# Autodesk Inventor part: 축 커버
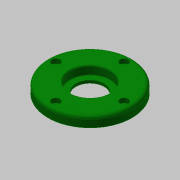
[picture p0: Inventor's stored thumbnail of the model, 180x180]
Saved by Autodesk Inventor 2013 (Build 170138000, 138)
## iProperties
Created: 2015-10
Part Number: 축 커버
Document SubType Name: Modeling
Designer: mdu
Density: 1 g/cm^3
Material: 일반
Author: mdu
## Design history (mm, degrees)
sketch "스케치1"
  geometry: C1 r 40 at (0, 0) reference; C2 r 26 at (0, 0) reference; 1 further point
  node "참조1"
  node "참조2"
extrude "돌출1" new body sketch "스케치1" distance "d0" = 10; taper "d1" = 0 deg
extrude "돌출2" join sketch "스케치1" distance "d2" = 4; taper "d3" = 0 deg
hole "구멍1" diameter "d6" = 27; stored, may be unused: countersink angle "d10" = 90 deg, drill point angle "d12" = 118 deg; dims "d7" = 6, "d8" = 38, "d9" = 8.3, "d11" = 8, "d33" = 10, "d34" = 10
sketch "스케치2"
  geometry: C1 r 20 at (0, 0); 1 further point
  constraints: 1 centre point, 1 coincident
  dimensions: "d13" = 40 diameter of C1
extrude "돌출3" cut sketch "스케치2" distance "d14" = 3; taper "d15" = 0 deg
sketch "스케치3"
  geometry: C1 r 1.621 at (0, 32.5) reference; 1 further point
hole "구멍2" sketch "스케치3" at (0, 32.5) diameter "d16" = 4.5; stored, may be unused: countersink angle "d20" = 90 deg, drill point angle "d22" = 118 deg; dims "d17" = 6, "d18" = 8, "d19" = 4.4, "d21" = 8
fillet "모깎기1" dims "d26" = 3, "d27" = 0.3
chamfer "모따기1" distance "d28" = 1; stored, may be unused: second distance "d29" = 2, angle "d30" = 45 deg
chamfer "모따기2" distance "d31" = 0.8; stored, may be unused: second distance "d32" = 2, angle "d35" = 30 deg
node "솔리드1"
pattern_circular "원형 패턴1" dims angle "d24" = 360 deg
node "참조3"
